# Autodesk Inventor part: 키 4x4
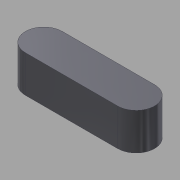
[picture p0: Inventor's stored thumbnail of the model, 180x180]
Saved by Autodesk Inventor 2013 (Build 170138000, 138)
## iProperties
Created: 2014-10
Part Number: 키 4x4
Document SubType Name: Modeling
Designer: KYOUNG IL JANG
Density: 1 g/cm^3
Mass: 0.210265 g
Surface Area: 2.35398 cm^2
Volume: 0.210265 cm^3
Material: 강철, 연강
Author: SeoGD™ [www.esajin.kr]
Revision Number: 1
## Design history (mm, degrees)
sketch "스케치1"
  geometry: L1 (-5, -2)-(5, -2); L2 (5, 2)-(-5, 2); A1 r 2 centre (5, 0) between (5, -2) and (5, 2); A2 r 2 centre (-5, 0) between (-5, 2) and (-5, -2); 2 further points
  constraints: 4 end point, 4 point on circle, 4 tangent, 2 centre point, 1 horizontal, 1 horizontal alignment, 1 midpoint, 1 parallel, 1 vertical alignment
  dimensions: "d0" = 4 distance between parallel lines of L1 L2; "d1" = 14 dimension on A1 A2
extrude "돌출1" new body sketch "스케치1" stored distance "d2" = 4; taper "d3" = 0 deg
node "솔리드1"
